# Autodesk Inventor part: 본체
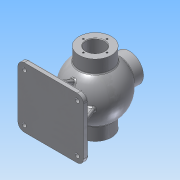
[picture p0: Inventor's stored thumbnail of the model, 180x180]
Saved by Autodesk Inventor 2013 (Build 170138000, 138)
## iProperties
Created: 2018-06
Part Number: 본체
Material: 알루미늄 6061
Document SubType Name: Modeling
Designer: Administrator
Density: 1 g/cm^3
Author: Administrator
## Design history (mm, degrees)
sketch "스케치1"
  geometry: L1 (31, -42.988)-(31, -68); L2 (31, -68)-(0, -68); L3 (0, -68)-(0, 68); L4 (0, 68)-(31, 68); L5 (31, 68)-(31, 42.988); A1 r 53 centre (0, 0) between (31, -42.988) and (31, 42.988); 2 further points
  constraints: 10 end point, 2 coincident, 2 parallel, 2 point on circle, 1 centre point, 1 collinear, 1 midpoint, 1 perpendicular, 1 vertical
  dimensions: "d0" = 106 diameter of A1; "d1" = 62 diameter of L1.end L3; "d2" = 62 diameter of L4.end L3; "d3" = 136 distance of L2.end L3.end
revolve "회전1" sketch "스케치1" stored, may be unused: angle "d4" = 90 deg
sketch "스케치2"
  geometry: L1 (-31, 68)-(31, 68) reference; L2 (31, 68)-(31, 42.988) reference; L3 (31, -42.988)-(31, -68) reference; L4 (31, -68)-(-31, -68) reference; L5 (-31, -68)-(-31, -42.988) reference; L6 (-31, 42.988)-(-31, 68) reference; L7 (17.5, -39.278)-(17.5, -50.25); L8 (17.5, -50.25)-(18.5, -50.25); L9 (18.5, -50.25)-(18.5, -52); L10 (18.5, -52)-(17.5, -52); L11 (17.5, -52)-(17.5, -68); L12 (17.5, 39.278)-(17.5, 68); L13 (17.5, 68)-(0, 68); L14 (0, 68)-(0, -68); L15 (17.5, -68)-(0, -68); A1 r 53 centre (0, 0) between (31, -42.988) and (31, 42.988) reference; A2 r 53 centre (0, 0) between (-31, 42.988) and (-31, -42.988) reference; A3 r 43 centre (0, 0) between (17.5, -39.278) and (17.5, 39.278); 1 further point
  constraints: 18 end point, 3 parallel, 2 collinear, 2 midpoint, 2 perpendicular, 2 point on circle, 2 point on line, 1 centre point, 1 coincident
  dimensions: "d5" = 86 diameter of A3; "d6" = 35 diameter of L12.end L14; "d7" = 35 diameter of L11.end L14; "d8" = 35 diameter of L7 L14; "d10" = 1.75 distance of L8.end L9.end; "d11" = 16 distance of L10.end L11.end; "d12" = 37 diameter of L9 L14
revolve "회전2" sketch "스케치2" stored, may be unused: angle "d13" = 90 deg
node "작업 평면1"
sketch "스케치3"
  geometry: C1 r 27 at (0, 0); 1 further point
  constraints: 1 centre point, 1 coincident
  dimensions: "d15" = 54 diameter of C1
extrude "돌출1" join sketch "스케치3" stored distance "d16" = 10; taper "d17" = 0 deg
sketch "스케치5"
  geometry: C1 r 27 at (0, 0) reference; C2 r 13 at (0, 0)
  constraints: 1 centre point, 1 coincident
  dimensions: "d18" = 26 diameter of C2
extrude "돌출2" cut sketch "스케치5" stored distance "d19" = 10; taper "d20" = 0 deg
node "작업 평면2"
sketch "스케치6"
  geometry: L1 (-62.5, 57.5)-(62.5, 57.5); L2 (62.5, 57.5)-(62.5, -57.5); L3 (62.5, -57.5)-(-62.5, -57.5); L4 (-62.5, -57.5)-(-62.5, 57.5); L5 (-62.5, 57.5)-(62.5, -57.5); L6 (62.5, 57.5)-(-62.5, -57.5); 1 further point
  constraints: 12 end point, 2 midpoint, 2 parallel, 1 horizontal, 1 perpendicular
  dimensions: "d22" = 125 distance of L2.end L3.end; "d23" = 115 distance of L1.end L2.end
extrude "돌출3" join sketch "스케치6" distance "d24" = 10; taper "d25" = 0 deg
sketch "스케치7"
  geometry: L1 (-62.5, -57.5)-(62.5, -57.5) reference; L2 (62.5, -57.5)-(62.5, 57.5) reference; L3 (62.5, 57.5)-(-62.5, 57.5) reference; L4 (-62.5, 57.5)-(-62.5, -57.5) reference; L5 (52.5, -4)-(-52.5, -4); L6 (-52.5, -4)-(-52.5, 4); L7 (-52.5, 4)-(52.5, 4); L8 (52.5, 4)-(52.5, -4); L9 (52.5, -4)-(-52.5, 4); L10 (-52.5, -4)-(52.5, 4); L11 (4, -47.5)-(-4, -47.5); L12 (-4, -47.5)-(-4, 47.5); L13 (-4, 47.5)-(4, 47.5); L14 (4, 47.5)-(4, -47.5); L15 (4, -47.5)-(-4, 47.5); L16 (-4, -47.5)-(4, 47.5); 3 further points
  constraints: 24 end point, 6 midpoint, 4 parallel, 2 horizontal, 2 perpendicular
  dimensions: "d26" = 8 distance of L7.end L5.start; "d28" = 8 distance of L12.end L13.end; "d29" = 10 distance between parallel lines of L3 L13; "d30" = 10 distance between parallel lines of L1 L11 (derived); "d31" = 10 distance between parallel lines of L2 L8; "d32" = 10 distance between parallel lines of L4 L6 (derived)
extrude "돌출4" join sketch "스케치7" stored distance "d33" = 10; taper "d34" = 0 deg
feature "면 기울기1" dims angle "d35" = 22 deg
sketch "스케치8"
  geometry: C1 r 4 at (-50.5, 45.5); C2 r 4 at (50.5, 45.5); C3 r 4 at (-50.5, -45.5); C4 r 4 at (50.5, -45.5); 1 further point
  constraints: 4 centre point, 2 horizontal alignment, 2 vertical alignment
  dimensions: "d36" = 8 diameter of C1; "d37" = 8 diameter of C2; "d38" = 8 diameter of C3; "d39" = 8 diameter of C4; "d40" = 101 distance of C2.centre C1.centre; "d41" = 50.5 horizontal distance of point (0, 0) C1.centre; "d42" = 91 distance of C4.centre C2.centre; "d43" = 45.5 vertical distance of point (0, 0) C2.centre
extrude "돌출5" cut sketch "스케치8" stored distance "d44" = 10; taper "d45" = 0 deg
sketch "스케치9"
  geometry: C1 r 4 at (-50.5, -45.5) reference; C2 r 4 at (-50.5, 45.5) reference; C3 r 4 at (50.5, 45.5) reference; C4 r 4 at (50.5, -45.5) reference; C5 r 6 at (-50.5, 45.5); C6 r 6 at (50.5, 45.5); C7 r 6 at (50.5, -45.5); C8 r 6 at (-50.5, -45.5); 1 further point
  constraints: 4 centre point, 4 coincident
  dimensions: "d46" = 12 diameter of C5; "d47" = 12 diameter of C6; "d48" = 12 diameter of C7; "d49" = 12 diameter of C8
extrude "돌출6" cut sketch "스케치9" distance "d50" = 3; taper "d51" = 0 deg
sketch "스케치10" dims "d52" = 45
  geometry: C1 r 31 at (0, 0) reference; 2 further points
  constraints: 2 vertical alignment, 1 coincident, 2 other
hole "구멍1" sketch "스케치10" at (0, 22.5) diameter "d53" = 3.242; stored, may be unused: countersink angle "d57" = 90 deg, drill point angle "d59" = 118 deg; dims "d54" = 12, "d55" = 4, "d56" = 2, "d58" = 15
sketch "스케치11" dims "d63" = 48
  geometry: C1 r 17.5 at (0, 0) reference; C2 r 31 at (0, 0) reference; 2 further points
  constraints: 2 vertical alignment, 1 coincident, 2 other
hole "구멍2" sketch "스케치11" at (0, 24) diameter "d64" = 3.242; stored, may be unused: countersink angle "d68" = 90 deg, drill point angle "d70" = 118 deg; dims "d65" = 16, "d66" = 4, "d67" = 2, "d69" = 19
sketch "스케치12" dims "d74" = 40
  geometry: C1 r 27 at (0, 0) reference; C2 r 13 at (0, 0) reference; 2 further points
  constraints: 2 vertical alignment, 1 coincident, 2 other
hole "구멍3" sketch "스케치12" at (0, 20) diameter "d75" = 3.242; stored, may be unused: countersink angle "d79" = 90 deg, drill point angle "d81" = 118 deg; dims "d76" = 9, "d77" = 4, "d78" = 2, "d80" = 11
fillet "모깎기1" dims "d85" = 12
node "작업 평면3"
sketch "스케치13"
  geometry: L1 (0, -27)-(0, 27) reference; 3 further points
  constraints: 1 coincident, 1 other
  dimensions: "d86" = 10 distance from line of point (10, 0) L1; "d87" = 27 vertical distance of point (10, 0) L1.start
feature "엠보싱1" sketch "스케치13" dims "d88" = 0.5, "d89" = 0
fillet "모깎기2" dims "d90" = 3
fillet "모깎기3" dims "d91" = 3
fillet "모깎기4" dims "d92" = 3
chamfer "모따기1" distance "d93" = 1; stored, may be unused: second distance "d94" = 2, angle "d95" = 45 deg
chamfer "모따기2" distance "d96" = 1; stored, may be unused: second distance "d97" = 2, angle "d98" = 45 deg
node "솔리드1"
pattern_circular "원형 패턴1" dims angle "d61" = 360 deg
pattern_circular "원형 패턴2" dims angle "d72" = 360 deg
pattern_circular "원형 패턴3" dims angle "d83" = 360 deg
node "절단 모서리 투영1"
other parameters: "d14" = 65, "d21" = -85
